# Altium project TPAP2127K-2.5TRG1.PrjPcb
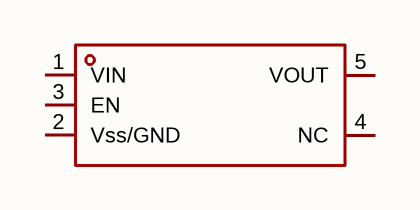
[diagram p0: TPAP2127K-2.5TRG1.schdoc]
1 sheet, 1 parts. Net scope: global (net labels, ports and power ports of the same name join across sheets).

## Sheet TPAP2127K-2.5TRG1.schdoc
size 127 x 101 mm

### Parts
U?  tpap2127k-2.5trg1  [SOT-23-5_L3.0-W1.7-P0.95-LS2.8-BR]  (value not drawn)

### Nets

Not connected (* = marked no-connect by the designer): U? 1(VIN) 2(Vss/GND) 3(EN) 4(NC) 5(VOUT)

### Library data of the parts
U? = tpap2127k-2.5trg1: 输出极性:正极;工作电压:7V;输出电压:2.5V;输出电流:350mA;电源纹波抑制比(PSRR):70dB@(1kHz);输出类型:固定;; Manufacturer: TECH PUBLIC(台舟); AddInBom: yes; ModelId: 0a2a1b8f50944f73965918ad6e5fe167; ModelName: SOT-23-5_L2.9-W1.6-H1.1-LS2.8-P0.95; ModelTransform: 114.173,109.636,0,180,0,0,0,0,0; Output Configuration: 正极; Voltage - Supply: 7V; Output Voltage: 2.5V; Output Current: 350mA; Voltage Dropout: 110mV@(100mA); standby current: 800nA; Output Type: 固定; Number of Outputs: 1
